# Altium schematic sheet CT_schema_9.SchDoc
size 278 x 170 mm
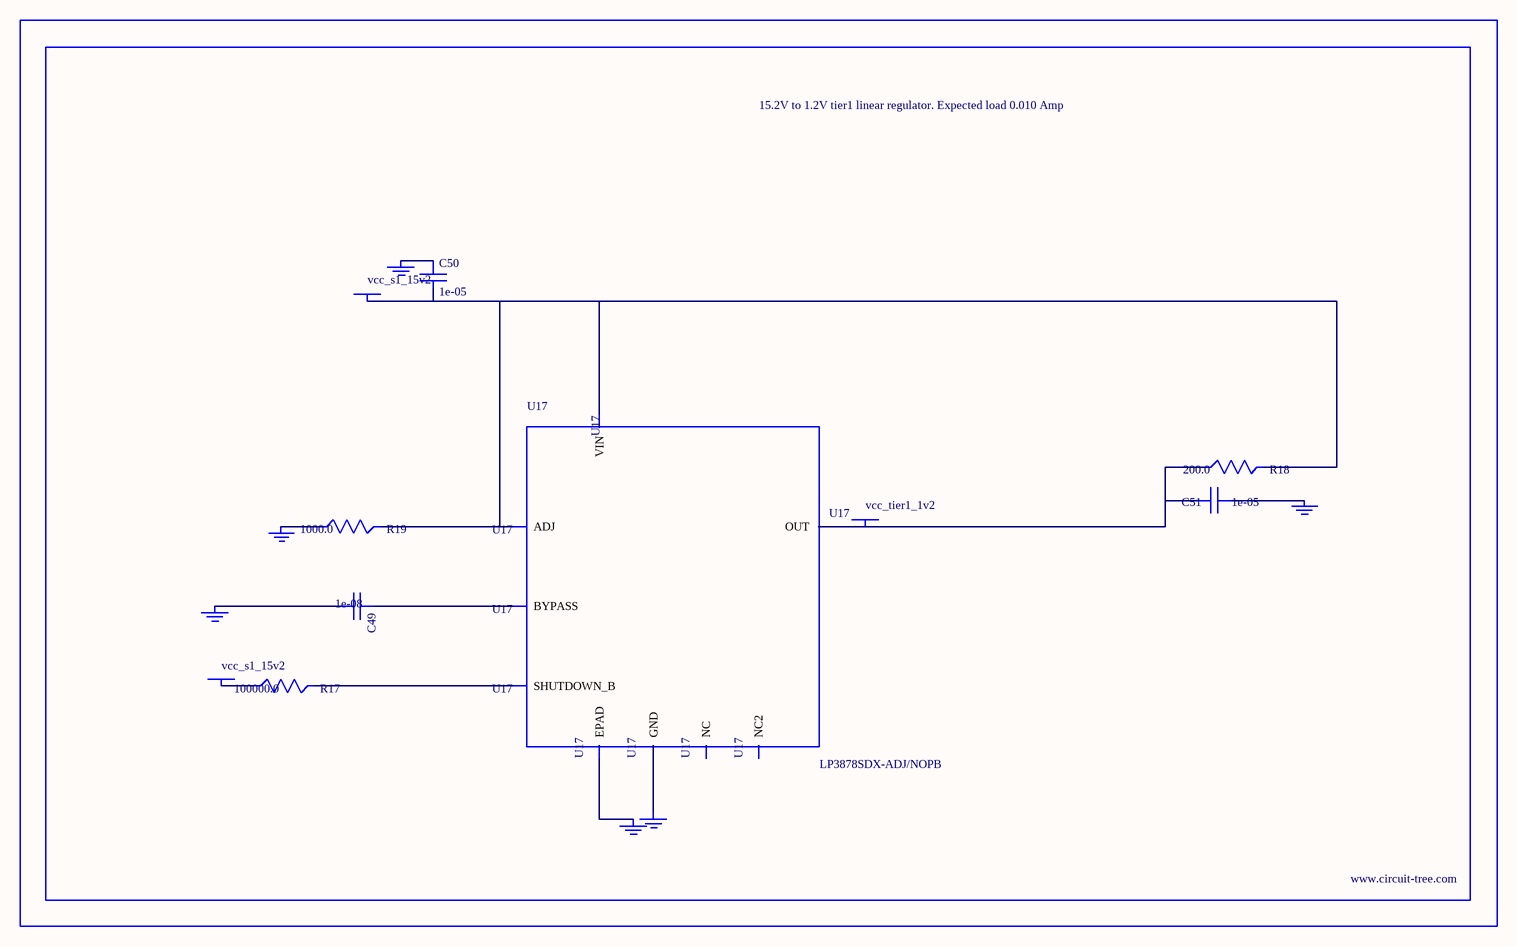
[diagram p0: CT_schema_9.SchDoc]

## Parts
BORDER8  (no value)
C49  1e-08  [C0402]
C50  1e-05  [C1210]
C51  1e-05  [C0805]
GND_INSTANCE_8_0  (no value)
GND_INSTANCE_8_1  (no value)
GND_INSTANCE_8_2  (no value)
GND_INSTANCE_8_3  (no value)
GND_INSTANCE_8_4  (no value)
GND_INSTANCE_8_5  (no value)
POWER_INSTANCE_8_0  vcc_s1_15v2
POWER_INSTANCE_8_1  vcc_s1_15v2
POWER_INSTANCE_8_2  vcc_tier1_1v2
R17  100000.0  [R0603]
R18  200.0  [R0603]
R19  1000.0  [R0603]
U17  LP3878SDX-ADJ/NOPB  [WSON-8]

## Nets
NetC49_1: C49.1 U17.1(BYPASS)
NetC49_2: C49.2 GND_INSTANCE_8_0.0(GND)
NetC50_1: C50.1 GND_INSTANCE_8_1.0(GND)
NetC50_2: C50.2 POWER_INSTANCE_8_0.0(PWR) R18.2 R19.2 U17.4(VIN) U17.6(ADJ)
NetC51_1: C51.1 GND_INSTANCE_8_2.0(GND)
NetC51_2: C51.2 POWER_INSTANCE_8_2.0(PWR) R18.1 U17.5(OUT)
NetGND_INSTANCE_8_3_0: GND_INSTANCE_8_3.0(GND) R19.1
NetGND_INSTANCE_8_4_0: GND_INSTANCE_8_4.0(GND) U17.PAD(EPAD)
NetGND_INSTANCE_8_5_0: GND_INSTANCE_8_5.0(GND) U17.3(GND)
NetPOWER_INSTANCE_8_1_0: POWER_INSTANCE_8_1.0(PWR) R17.1
NetR17_2: R17.2 U17.8(SHUTDOWN_B)

Not connected (* = marked no-connect by the designer): U17 2(NC) 7(NC2)

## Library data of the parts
BORDER8 = BORDER_PAGE8
C49 = C0402C103K3RAC
C50 = C1210C106K5PACTU
C51 = GRM219R60J106ME19D
GND_INSTANCE_8_0-GND_INSTANCE_8_5 = GND
POWER_INSTANCE_8_0-POWER_INSTANCE_8_2 = PWR
R17 = RC0603JR-07100KL
R18 = RC0603JR-07200RL
R19 = RC0603JR-071KL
